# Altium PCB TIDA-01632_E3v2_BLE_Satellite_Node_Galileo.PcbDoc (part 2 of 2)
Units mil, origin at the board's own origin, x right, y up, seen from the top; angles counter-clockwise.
Board outline 3000 x 1875.2 mil, 6 copper layers (Top Layer, Layer2, Layer3, Layer4, Layer5, Bottom Layer), stack 33.151 mil thick; 76 components, 48 nets, 235 pads, 260 vias.
Unrouted connection lines stored in the file: 1.
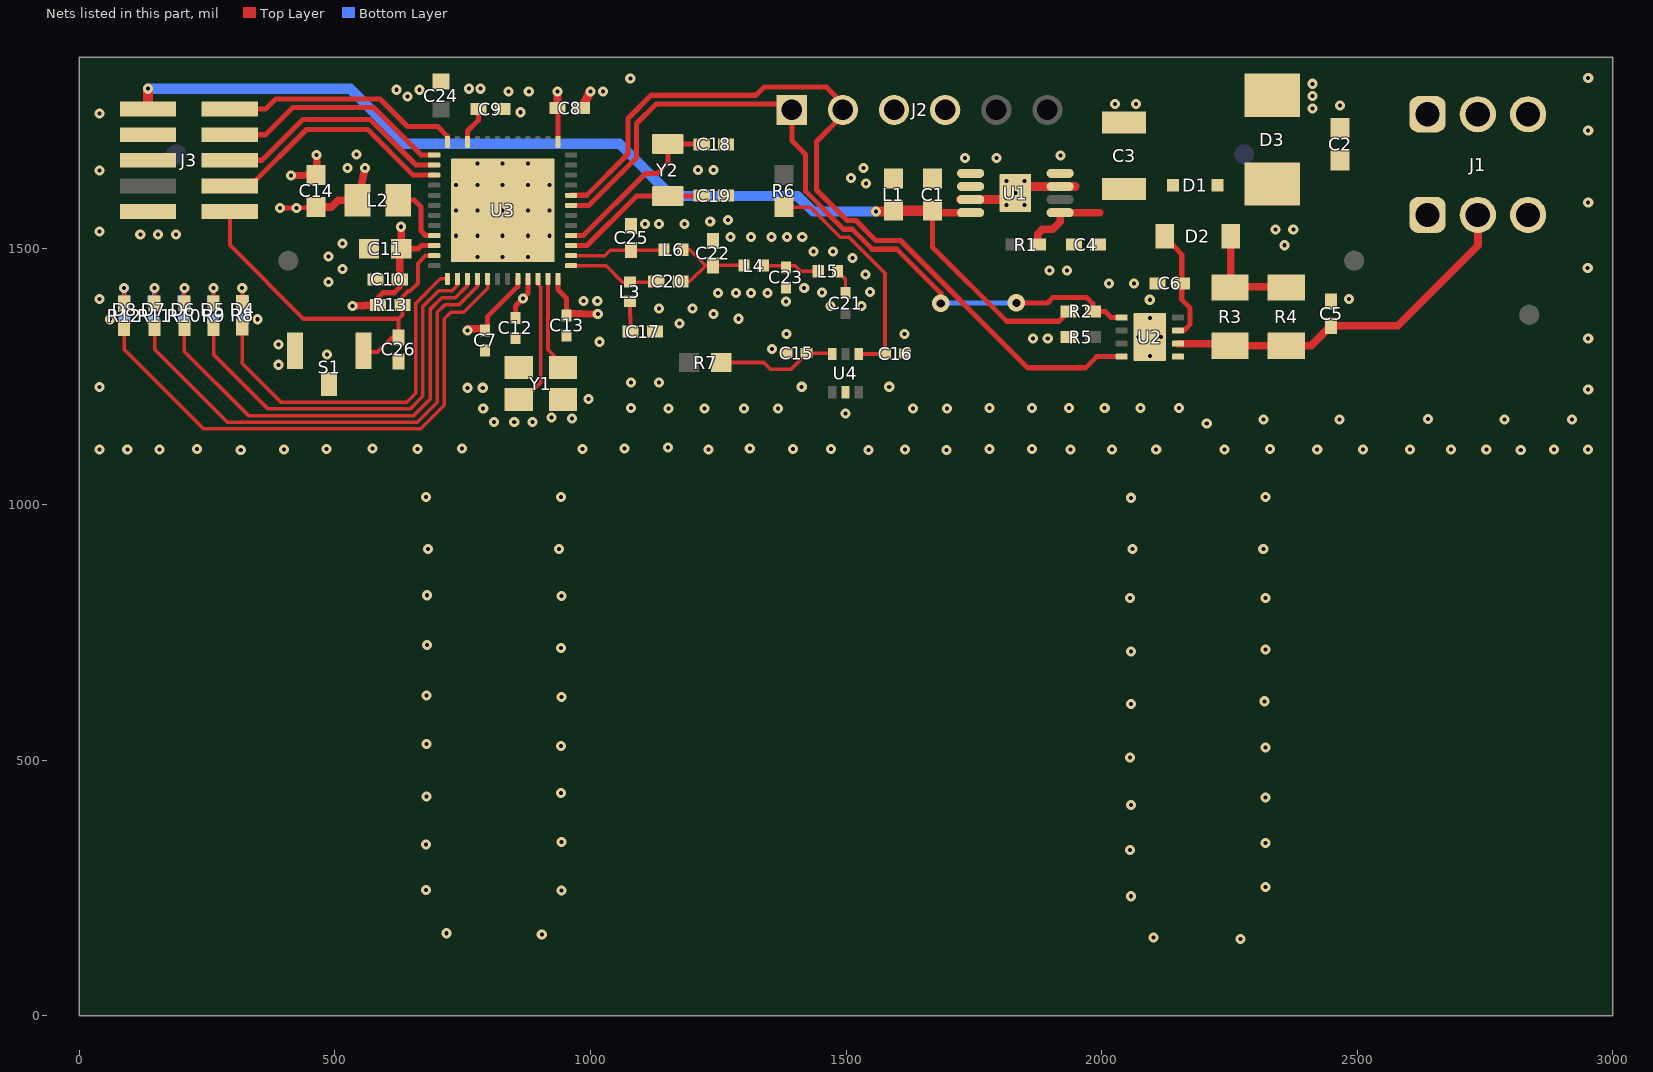
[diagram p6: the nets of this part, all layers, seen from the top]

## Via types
v1: diameter 19.68, hole 7.87, Top Layer to Bottom Layer, tented both sides, 192 vias
v2: diameter 19.68, hole 7.87, Top Layer to Bottom Layer, 63 vias
v3: diameter 34, hole 16, Top Layer to Bottom Layer, tented both sides, 4 vias
v4: diameter 19.68/19.68/19.68/19.68/19.68/19.68 (per signal layer), hole 7.87, Top Layer to Bottom Layer, tented both sides, 1 vias

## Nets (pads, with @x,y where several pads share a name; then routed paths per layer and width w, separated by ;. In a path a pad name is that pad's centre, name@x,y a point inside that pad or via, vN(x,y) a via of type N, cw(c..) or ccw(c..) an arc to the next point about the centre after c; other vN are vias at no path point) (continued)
GND: C1.2 C2.2 C3.1 C4.2 C5.2 C6.2 C7.2 C8.2 C9.2 C10.2 C11.2 C12.2 C13.2 C14.2 C15.2 C16.2 C17.2 C18.2 C19.2 C22.2 C23.2 C24.2 C25.2 C26.2 D3.1 D4.1 D5.2 D6.2 D7.2 D8.1 J1.3 J2.3 J3.3 J3.5 J3.9 R5.1 S1.2 S1.3 U1.3 U1.4 U1.5 U1.6 U1.7 U1.9 U2.5 U2.9@2094.27,1327.59 U3.49@828.41,1575.38 U4.2 Y1.2 Y1.4 | length 322.8
  Top Layer w15: v1(414.41,1643.38) C14.2@463.41,1644.87 v1(464.41,1683.38)
  Top Layer w18: C8.2@983.03,1775.38 v1(1000.41,1808.38) ; U1.7@1724.65,1596.58 U1.7@1743.81,1596.58 U1.9@1818.61,1596.58 ; U1.9@1844.2,1622.17 U1.3@1919.01,1622.17 1948.2,1622.17
  other v1: 2271.75,150.16 2101.93,152.95 904.86,158.51 718.34,161.3 2057.39,233.68 943.84,244.81 677.97,246.21 2320.47,251.77 2056,324.15 677.97,335.29 2320.47,338.07 943.84,339.47 2057.39,411.85 2320.47,427.16 679.37,428.55 942.44,435.51 2056,505.11 2320.47,524.59 942.44,527.38 679.37,531.55 2057.39,609.5 2319.07,615.07 943.84,623.42 679.37,626.21 2057.39,712.51 2320.47,716.68 942.44,719.47 680.76,725.03 2056,816.9 2320.47,816.9 943.84,821.08 680.76,822.47 682.15,912.95 938.27,912.95 2060.17,912.95 2316.29,912.95 2057.39,1013.17 677.97,1014.56 942.44,1014.56 2320.47,1014.56 39.95,1107.4 2020.26,1107.4 2106.88,1107.4 2205.71,1158.46 811,1161 851,1161 2316.91,1166.57 2465.54,1166.57 2788.37,1166.57 2920.26,1166.57 964,1168 2638.76,1167.56 924,1170 1499.02,1178.15 790.34,1188.23 1079.69,1188.38 1153.18,1188.11 1223.46,1188.11 1300.2,1187.99 1367.13,1187.99 1630.87,1187.99 1697.8,1187.99 1780.51,1188.98 1864.17,1188.98 1935.86,1189.11 2006.15,1189.11 2076.44,1189.11 2151.57,1188.98 996,1206 2952,1225 759.41,1228.38 789.41,1228.38 40,1230 1413.39,1230.32 1079.41,1238.38 1134.41,1238.38 389.41,1273.38 484.41,1293.38 1355.3,1304.37 389.41,1313.38 1017.41,1318.38 1865.67,1325.04 1894.67,1325.04 2952,1325 1383.84,1333.9 1614.16,1333.9 1174.41,1354.38 60.02,1362.44 348.41,1362.44 1289.41,1363.38 1240.41,1372.38 1134.41,1383.38 1199.41,1383.38 1469.47,1388.03 1530.5,1388.03 1382.86,1396.89 2094.27,1400.59 40,1402 2484.24,1401.81 1249.41,1413.38 1284.55,1413.38 1314.41,1413.38 1346.44,1413.62 1452.74,1414.61 1547.23,1415.59 1418.29,1423.46 2014.27,1432.59 2063.27,1432.59 487.41,1435.38 1538.37,1450.04 1898.41,1457.38 1932.41,1457.38 515.41,1460.38 2951,1463 1512.78,1482.52 487.41,1485.38 1436.01,1495.32 1474.39,1495.32 2357.41,1507.2 515.41,1510.38 1274.41,1523.38 1314.41,1523.38 1354.41,1523.38 1384.41,1523.38 1414.41,1523.38 119.41,1528.38 154.41,1528.38 189.55,1528.38 40,1534 2339.98,1537.64 2374.98,1537.64 1106.41,1548.38 1134.41,1548.38 1184.41,1548.38 1234.41,1553.38 1269.41,1556.38 2952,1591 40,1653 1210.41,1654.38 1240.41,1654.38 1733,1678 1794,1678 1919.41,1682.38 2952,1732 40,1765 863.41,1767.38 2412.39,1774.84 2466.52,1780.75 2026.56,1783.7 2066.91,1783.7 642.41,1798.38 2412.39,1799.45 839.41,1808.38 879.41,1808.38 1024.41,1808.38 620.41,1811.38 665.41,1811.38 2412.39,1823.07 1078,1833 2952,1834
  other v2: 316,1107 1544,1107 1697,1107 2240.73,1107.4 2421.84,1107.4 2511.4,1107.4 2602.94,1107.4 2683.65,1107.4 2752.54,1107.4 2820,1107 2885.42,1107.4 2951.36,1107.4 94,1108 157,1108 401,1108 1231,1108 1615,1108 1939,1108 230.22,1108.53 483.56,1108.53 661.73,1108.53 748.61,1109.36 984.66,1108.53 1396,1109 1471,1109 1781,1109 1864,1109 2329.27,1108.53 574.03,1109.92 1066.78,1109.92 1311.76,1109.92 1151.69,1111.32 887,1161 2094.27,1290.19 2072.61,1327.59 2115.92,1327.59 2094.27,1364.99 778.8,1483.84 828.41,1483.84 878.01,1483.84 736.87,1525.77 778.8,1525.77 828.41,1525.77 878.01,1525.77 919.94,1525.77 736.87,1575.38 778.8,1575.38 828.41,1575.38 878.01,1575.38 919.94,1575.38 1813.69,1585.75 1849.12,1585.75 1831.41,1609.38 736.87,1624.98 778.8,1624.98 828.41,1624.98 878.01,1624.98 919.94,1624.98 1813.69,1633 1849.12,1633 778.8,1666.91 828.41,1666.91 878.01,1666.91
  other v4: 1584.61,1230.32
LED_Blue: R9.2 U3.38 | length 789.2
  Top Layer w7: R9.2@262.78,1345.71 262.78,1293.54 369.32,1187 647.64,1187 672.28,1211.64 672.28,1387.45 703.21,1418.38 729.41,1418.38 739.83,1428.79 U3.38@739.83,1441.52
LED_Green: R8.2 U3.37 | length 706.6
  Top Layer w7: R8.2@318.88,1346.69 318.88,1275.83 394.71,1200 640.84,1200 658.28,1217.44 658.28,1393.25 706.55,1441.52 U3.37@720.14,1441.52
LED_Orange: R11.2 U3.40 | length 953.9
  Top Layer w7: R11.2@147.62,1339.14 147.62,1303.39 290.01,1161 661.23,1161 700.28,1200.04 700.28,1375.85 714.8,1390.38 742.44,1390.38 774.38,1422.32 ; 774.38,1422.35 779.2,1427.16 U3.40@779.2,1441.52
LED_Red: R12.2 U3.41 | length 1048.5
  Top Layer w7: R12.2@87.81,1344.81 87.81,1303.16 242.97,1148 668.03,1148 714.28,1194.25 714.28,1363.25 727.41,1376.38 752.41,1376.38 798.88,1422.85 U3.41@798.88,1441.52
LED_Yellow: R10.2 U3.39 | length 873.5
  Top Layer w7: R10.2@205.69,1345.71 205.69,1299.45 331.14,1174 654.43,1174 686.28,1205.84 686.28,1381.65 709.01,1404.38 735.21,1404.38 736.21,1405.38 736.44,1405.38 754.7,1423.63 759.51,1428.48 U3.39@759.51,1441.52
LIN: C5.1 J1.2 R3.1 R4.1 U2.6 | length 740.1
  Top Layer w15: U2.6@2149.38,1314.79 R3.1@2246.97,1314.79 ; R3.1@2251.27,1310.5 R4.1@2361.27,1310.5 2409.66,1310.5 C5.1@2448.8,1349.65 2579.28,1349.65 2736.2,1506.57 J1.2@2736.2,1582.91
NetC17_1: C17.1 L3.2 | length 59.9
  Top Layer w7.87: L3.2@1077.41,1397.67 1077.41,1368.38 1078.79,1367 C17.1@1078.79,1338.38
NetC20_1: C20.1 C22.1 L4.1 L6.2 | length 194.9
  Top Layer w6.75: C20.1@1176.03,1436.38 1194.41,1436.38 1225.41,1467.38 ; L6.2@1181.11,1498.38 1194.41,1498.38 1225.41,1467.38 ; 1226.03,1468 1225.41,1467.38 ; L4.1@1300.09,1468 C22.1@1239.41,1468 1225.41,1467.38
NetC21_2: C21.2 L5.2 | length 45.4
  Top Layer w6.75: L5.2@1483.11,1456.38 1499,1440.48 C21.2@1499,1417.56
NetC23_1: C23.1 L4.2 L5.1 | length 112.2
  Top Layer w6.75: L4.2@1338.11,1467.38 1400.41,1467.38 1411.41,1456.38 L5.1@1445.71,1456.38
NetD2_1: D2.1 R3.2 R4.2 | length 205.5
  Top Layer w15: D2.1@2252.73,1524.56 2252.73,1426.14 R4.2@2359.8,1426.14
NetD4_2: D4.2 R8.1 | length 54.5
  Top Layer w7: R8.1@318.88,1393.94 v1(318.88,1423.46)
  Bottom Layer w7: v1(318.88,1423.46) 319.87,1422.48 D4.2@319.87,1398.86
NetD5_1: D5.1 R9.1 | length 55.5
  Top Layer w7: R9.1@262.78,1392.95 v1(262.78,1423.46)
  Bottom Layer w7: D5.1@261.8,1398.86 261.8,1422.48 v1(262.78,1423.46)
NetD6_1: D6.1 R10.1 | length 55.9
  Top Layer w7: R10.1@205.69,1392.95 v1(205.69,1423.46)
  Bottom Layer w7: D6.1@203.72,1398.86 203.72,1421.5 v1(205.69,1423.46)
NetD7_1: D7.1 R11.1 | length 55.9
  Top Layer w7: R11.1@147.62,1392.95 v1(147.62,1423.46)
  Bottom Layer w7: D7.1@145.65,1398.86 145.65,1421.5 v1(147.62,1423.46)
NetD8_2: D8.2 R12.1 | length 55.2
  Top Layer w7: R12.1@87.81,1392.7 v1(87.81,1423.24)
  Bottom Layer w7: v1(87.81,1423.24) 88.57,1422.48 D8.2@88.57,1398.86
NetL2_1: L2.1 U3.33 | length 126.3
  Top Layer w10: L2.1@624.41,1595.38 655.41,1595.38 668.41,1582.38 668.41,1535.38 677.62,1526.16 U3.33@694.55,1526.16
NetU3_46: U3.46 Y1.3 | length 264.3
  Top Layer w7: Y1.3@861.1,1196.88 902.99,1238.77 902.99,1425.09 897.31,1430.77 U3.46@897.31,1441.52
NetU3_47: U3.47 Y1.1 | length 182.2
  Top Layer w7: U3.47@916.99,1441.52 916.99,1302.79 Y1.1@947.71,1272.07
nRESET: C26.1 J3.10 R13.1 S1.1 U3.35 | length 726.3
  Top Layer w7.87: J3.10@294.53,1573.38 294.53,1507.26 438.41,1363.38 624.41,1363.38 ; S1.1@566.34,1298.38 583.41,1298.38 612.03,1327 C26.1@624.41,1327 624.41,1363.38 ; U3.35@694.55,1486.79 677.83,1486.79 662.41,1471.38 662.41,1432.73 647.31,1417.63 643.66,1417.63 632.03,1406 R13.1@632.03,1390.38 632.03,1371 624.41,1363.38
RF_N: C25.1 L6.1 U3.2 | length 186.2
  Top Layer w6.75: U3.2@962.27,1486.79 1027.83,1486.79 1038.79,1497.75 C25.1@1079.41,1497.75 1143.09,1497.75 L6.1@1143.71,1498.38
RF_P: C20.2 L3.1 U3.1 | length 178.5
  Top Layer w6.75: U3.1@962.27,1467.11 1030.68,1467.11 1062.71,1435.08 L3.1@1077.41,1435.08 C20.2@1127.49,1435.08
RXD_LIN: J2.1 R2.1 U2.1 U3.7 | length 1486
  Top Layer w10: U3.7@962.27,1585.22 997.17,1585.22 1090.41,1678.46 1090.41,1745.38 1128.73,1783.7 1394.67,1783.7 1394.67,1710.87 1421.06,1684.47 1421.06,1612.68 1495.35,1538.4 1512.3,1538.4 1551.32,1499.38 1599.37,1499.38 1685.41,1413.33 v3(1685.41,1393.38) ; v3(1833.41,1394.38) 1894.05,1394.38 1904.27,1404.59 1971.27,1404.59 1982.89,1392.97 R2.1@1982.89,1377.59 2007.27,1377.59 2018.88,1365.97 U2.1@2039.15,1365.97
  Bottom Layer w10: v3(1685.41,1393.38) 1686.41,1394.38 v3(1833.41,1394.38)
TCK: J3.4 U3.25 | length 460.4
  Top Layer w10: J3.4@294.53,1723.38 364.41,1723.38 417.41,1776.38 576.41,1776.38 669.14,1683.64 U3.25@694.55,1683.64
TDI: J3.8 U3.27 | length 482.5
  Top Layer w10: J3.8@294.53,1623.38 334.41,1623.38 444.41,1733.38 564.41,1733.38 653.51,1644.27 U3.27@694.55,1644.27
TDO: J3.6 U3.26 | length 470.2
  Top Layer w10: J3.6@294.53,1673.38 357.41,1673.38 437.41,1753.38 569.41,1753.38 658.83,1663.96 U3.26@694.55,1663.96
TMS: J3.2 U3.24 | length 475.4
  Top Layer w10: J3.2@294.53,1773.38 364.41,1773.38 384.41,1793.38 588.41,1793.38 642.41,1739.38 701.41,1739.38 720.14,1720.64 U3.24@720.14,1709.23
TXD_LIN: J2.2 U2.4 U3.8 | length 1614.7
  Top Layer w10: U3.8@962.27,1604.9 992.81,1604.9 1073.41,1685.5 1073.41,1755.38 1118.73,1800.7 1323.7,1800.7 1340,1817 1461.37,1817 1494.67,1783.7 1494.67,1762.64 1442.41,1710.38 1442.41,1615.38 1502.39,1555.4 1519.35,1555.4 1558.37,1516.38 1606.41,1516.38 1855.2,1267.59 1968.81,1267.59 1990.42,1289.2 U2.4@2039.15,1289.2
V3p3: C1.1 J3.1 L1.2 R2.2 U1.8 | length 2149
  Top Layer w10: C1.1@1669.41,1574.88 1669.41,1503.38 1814.28,1358.5 1916.56,1358.5 R2.2@1935.64,1377.59
  Top Layer w15: C1.1@1673.3,1570.99 U1.8@1743.81,1570.99
  Top Layer w20: J3.1@134.29,1773.38 v1@134.29,1813.26 ; v1(1558.41,1573.38) L1.2@1591.4,1573.38 ; L1.2@1592.91,1574.88 C1.1@1669.41,1574.88
  Bottom Layer w20: v1(134.41,1813.38) 530.41,1813.38 637.84,1705.94 1056.84,1705.94 1159.41,1603.38 1405.41,1603.38 1435.41,1573.38 v1(1558.41,1573.38)
VBATT: C2.1 D1.2 D3.2 J1.1
VCTRL1: C16.1 R6.2 U4.4 | length 460.9
  Top Layer w7: R6.2@1378.58,1581.88 1429.94,1581.88 1488.93,1522.9 1505.88,1522.9 1576.32,1452.46 C16.1@1576.32,1295.32 ; U4.4@1524.59,1294.4 1575.4,1294.4 C16.1@1576.32,1295.32 ; C16.1@1576.32,1295 C16.1@1576.32,1295.32
VCTRL2: C15.1 R7.2 U4.6 | length 234
  Top Layer w7: R7.2@1255.89,1277.8 1339.2,1277.8 1352,1265 1393,1265 C15.1@1423,1295 ; C15.1@1422.68,1296 U4.6@1471.81,1296
VDDR: C12.1 C13.1 C14.1 L2.2 U3.45 U3.48 | length 457.8
  Top Layer w10: v1(392.41,1580.38) v1(425.41,1580.38) C14.1@463.41,1581.88 C14.1@446.03,1581.88 ; C12.1@853.41,1369 853.41,1388.38 v1(868.41,1403.38) 877.62,1412.59 U3.45@877.62,1441.52 ; U3.48@936.68,1441.52 936.68,1420.11 953.41,1403.38 C13.1@953.41,1374
  Top Layer w15: C14.1@463.41,1581.88 492.91,1581.88 506.41,1595.38 L2.2@544.41,1595.38 v1(559.41,1658.38) ; C13.1@953.41,1374 v1(1014.41,1372.38)
  other v1: 986.41,1398.38 1013.41,1398.38 524.41,1658.38 542.41,1684.38
VDDS: C7.1 C8.1 C9.1 C10.1 C11.1 J2.4 L1.1 R13.2 U3.13 U3.22 U3.34 U3.44 | length 630.8
  Top Layer w10: R13.2@584.79,1390.38 584.79,1404.75 594.22,1414.19 616.22,1414.19 627.03,1425 C10.1@627.03,1440.38 ; C11.1@627.03,1497.5 C11.1@629.9,1500.38 663.41,1500.38 669.51,1506.48 U3.34@694.55,1506.48 ; U3.22@759.51,1709.23 759.51,1730.48 780.79,1751.75 C9.1@780.79,1773.38 ; C7.1@798.41,1344 798.41,1367.42 857.94,1426.94 U3.44@857.94,1441.52 ; U3.13@936.68,1709.23 C8.1@936.68,1774.49
  Top Layer w15: v1(534.41,1388.38) R13.2@584.79,1390.38 ; C10.1@627.03,1440.38 C11.1@627.03,1497.5 ; C11.1@629.9,1500.38 v1@629.9,1542.88 ; v1(759.41,1340.38) 763.03,1344 C7.1@794,1344 ; C8.1@935.79,1775.38 v1@935.79,1808
  other v1: 629.41,1543.38 1539.55,1628.38 1509.41,1638.38 1534.41,1658.38 935.41,1808.38 762.41,1813.38 785.41,1813.38
VSUP: C3.2 C4.1 C6.1 D1.1 D2.2 R1.1 U1.1 U2.7 | length 390
  Top Layer w10: D2.2@2123.8,1524.56 2156.89,1489 C6.1@2156.89,1432.59 2156.89,1400.79 2173.27,1384.41 2173.27,1352.59 2161.06,1340.38 U2.7@2149.38,1340.38
  Top Layer w15: R1.1@1875.06,1508.51 1875.06,1529.03 1884.41,1538.38 1904.41,1538.38 1919.01,1552.97 U1.1@1919.01,1570.99 1995.93,1570.99
X32K_Q1: C19.1 U3.3 Y2.2 | length 294.4
  Top Layer w10: U3.3@962.27,1506.48 993.51,1506.48 1090.23,1603.19 Y2.2@1151.41,1603.19 C19.1@1216.6,1603.19
X32K_Q2: C18.1 U3.4 Y2.1 | length 350.4
  Top Layer w10: U3.4@962.27,1526.16 986.2,1526.16 1107.65,1647.62 1130.65,1647.62 1151.41,1668.38 Y2.1@1151.41,1705.56 C18.1@1216.6,1705.56
pads on no net: FID1.1 FID2.1 FID3.1 FID4.1 FID5.1 FID6.1 J3.7 LBL1.0 U2.3 U2.8 U2.9@2094.27,1302.59 U2.9@2094.27,1352.59 U3.5 U3.12 U3.14 U3.15 U3.16 U3.17 U3.18 U3.19 U3.20 U3.21 U3.28 U3.29 U3.30 U3.31 U3.32 U3.36 U3.43 U3.49@754,1500.97 U3.49@754,1550.57 U3.49@754,1600.18 U3.49@754,1649.78 U3.49@803.6,1500.97 U3.49@803.6,1550.57 U3.49@803.6,1600.18 U3.49@803.6,1649.78 U3.49@853.21,1500.97 U3.49@853.21,1550.57 U3.49@853.21,1600.18 U3.49@853.21,1649.78 U3.49@902.82,1500.97 U3.49@902.82,1550.57 U3.49@902.82,1600.18 U3.49@902.82,1649.78

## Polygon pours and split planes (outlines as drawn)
GND on Layer2 "LAYER2-GND 4" (solid, pour order 541): 220.47,1072.85 220.47,88.58 181.08,88.61 181.11,1072.85 141.74,1072.85 141.72,88.61 102.35,88.61 102.35,1072.83 62.99,1072.83 62.99,88.61 23.62,88.61 23.59,1072.85 23.59,1112.22 220.47,1112.22 220.47,1072.85
GND on Layer2 "LAYER2-GND 5" (solid, pour order 539): 1440.93,1072.85 1440.93,88.58 1401.56,88.58 1401.56,1072.85 1362.2,1072.85 1362.2,88.58 1322.83,88.58 1322.83,1072.85 1283.47,1072.85 1283.44,88.61 1244.08,88.61 1244.11,1072.85 1204.71,1072.83 1204.71,88.61 1165.35,88.61 1165.32,1072.85 1125.96,1072.85 1125.99,88.61 1086.59,88.58 1086.59,1072.85 1047.23,1072.85 1047.23,88.58 1007.87,88.58 1007.87,1072.85 968.5,1072.85 968.47,206.7 850.38,88.61 771.65,88.61 653.53,206.73 653.53,1072.85 614.17,1072.85 614.17,88.58 574.8,88.58 574.8,1072.85 535.44,1072.85 535.41,88.61 496.05,88.61 496.05,1072.83 456.68,1072.83 456.68,88.61 417.32,88.61 417.29,1072.85 377.93,1072.85 377.96,88.61 338.56,88.58 338.56,1072.85 299.2,1072.85 299.2,88.58 259.84,88.58 259.84,1072.85 220.47,1072.85 220.47,88.58 181.08,88.61 181.11,1072.85 181.11,1112.22 1440.93,1112.22 1440.93,1072.85
GND on Layer2 "LAYER2-GND 7" (solid, pour order 537): 1598.41,1072.83 1598.41,88.61 1559.05,88.61 1559.05,1072.83 1519.65,1072.85 1519.68,88.61 1480.29,88.58 1480.29,1072.85 1440.93,1072.85 1440.93,88.58 1401.56,88.58 1401.56,1072.85 1401.56,1112.22 1598.44,1112.22 1598.41,1072.83
GND on Layer2 "LAYER2-GND 9" (solid, pour order 535): 2818.89,1072.85 2818.89,88.58 2779.53,88.58 2779.53,1072.85 2740.17,1072.85 2740.14,88.61 2700.77,88.61 2700.77,1072.83 2661.41,1072.83 2661.41,88.61 2622.05,88.61 2622.02,1072.85 2582.65,1072.85 2582.65,88.58 2543.29,88.58 2543.29,1072.85 2503.92,1072.85 2503.92,88.58 2464.56,88.58 2464.56,1072.85 2425.2,1072.85 2425.2,88.58 2385.8,88.61 2385.83,1072.85 2346.47,1072.85 2346.44,206.7 2228.35,88.61 2149.59,88.58 2031.47,206.7 2031.5,1072.85 1992.14,1072.85 1992.11,88.61 1952.74,88.61 1952.74,1072.83 1913.38,1072.83 1913.38,88.61 1874.02,88.61 1873.99,1072.85 1834.62,1072.85 1834.62,88.58 1795.26,88.58 1795.26,1072.85 1755.89,1072.85 1755.89,88.58 1716.53,88.58 1716.53,1072.85 1677.17,1072.85 1677.17,88.58 1637.77,88.61 1637.8,1072.85 1598.41,1072.83 1598.41,88.61 1559.05,88.61 1559.05,1072.83 1559.02,1112.22 2818.89,1112.22 2818.89,1072.85
GND on Layer2 "LAYER2-GND 4" (solid, pour order 533): 2976.38,1072.83 2976.38,88.55 2936.99,88.58 2937.01,1072.83 2897.65,1072.83 2897.62,88.58 2858.26,88.58 2858.26,1072.8 2818.89,1072.8 2818.89,88.58 2779.53,88.58 2779.5,1072.83 2779.5,1112.19 2976.38,1112.19 2976.38,1072.83
GND on Layer2 "LAYER2_GND_P240" (solid, remove dead copper, pour order 240): 24,1108 23,1890 2975.38,1890 2975.38,1108
GND on Layer5 "LAYER5-GND 6" (solid, pour order 551): 2818.89,1072.85 2818.89,88.58 2779.53,88.58 2779.53,1072.85 2740.17,1072.85 2740.14,88.61 2700.77,88.61 2700.77,1072.83 2661.41,1072.83 2661.41,88.61 2622.05,88.61 2622.02,1072.85 2582.65,1072.85 2582.65,88.58 2543.29,88.58 2543.29,1072.85 2503.92,1072.85 2503.92,88.58 2464.56,88.58 2464.56,1072.85 2425.2,1072.85 2425.2,88.58 2385.8,88.61 2385.83,1072.85 2346.47,1072.85 2346.44,206.7 2228.35,88.61 2149.59,88.58 2031.47,206.7 2031.5,1072.85 1992.14,1072.85 1992.11,88.61 1952.74,88.61 1952.74,1072.83 1913.38,1072.83 1913.38,88.61 1874.02,88.61 1873.99,1072.85 1834.62,1072.85 1834.62,88.58 1795.26,88.58 1795.26,1072.85 1755.89,1072.85 1755.89,88.58 1716.53,88.58 1716.53,1072.85 1677.17,1072.85 1677.17,88.58 1637.77,88.61 1637.8,1072.85 1598.41,1072.83 1598.41,88.61 1559.05,88.61 1559.05,1072.83 1559.02,1112.22 2818.89,1112.22 2818.89,1072.85
GND on Layer5 "LAYER5-GND 7" (solid, pour order 549): 1598.41,1072.83 1598.41,88.61 1559.05,88.61 1559.05,1072.83 1519.65,1072.85 1519.68,88.61 1480.29,88.58 1480.29,1072.85 1440.93,1072.85 1440.93,88.58 1401.56,88.58 1401.56,1072.85 1401.56,1112.22 1598.44,1112.22 1598.41,1072.83
GND on Layer5 "LAYER5-GND 8" (solid, pour order 547): 1440.93,1072.85 1440.93,88.58 1401.56,88.58 1401.56,1072.85 1362.2,1072.85 1362.2,88.58 1322.83,88.58 1322.83,1072.85 1283.47,1072.85 1283.44,88.61 1244.08,88.61 1244.11,1072.85 1204.71,1072.83 1204.71,88.61 1165.35,88.61 1165.32,1072.85 1125.96,1072.85 1125.99,88.61 1086.59,88.58 1086.59,1072.85 1047.23,1072.85 1047.23,88.58 1007.87,88.58 1007.87,1072.85 968.5,1072.85 968.47,206.7 850.38,88.61 771.65,88.61 653.53,206.73 653.53,1072.85 614.17,1072.85 614.17,88.58 574.8,88.58 574.8,1072.85 535.44,1072.85 535.41,88.61 496.05,88.61 496.05,1072.83 456.68,1072.83 456.68,88.61 417.32,88.61 417.29,1072.85 377.93,1072.85 377.96,88.61 338.56,88.58 338.56,1072.85 299.2,1072.85 299.2,88.58 259.84,88.58 259.84,1072.85 220.47,1072.85 220.47,88.58 181.08,88.61 181.11,1072.85 181.11,1112.22 1440.93,1112.22 1440.93,1072.85
GND on Layer5 "LAYER5-GND 9" (solid, pour order 545): 220.47,1072.85 220.47,88.58 181.08,88.61 181.11,1072.85 141.74,1072.85 141.72,88.61 102.35,88.61 102.35,1072.83 62.99,1072.83 62.99,88.61 23.62,88.61 23.59,1072.85 23.59,1112.22 220.47,1112.22 220.47,1072.85
GND on Layer5 "LAYER2-GND 4" (solid, pour order 543): 2976.38,1072.83 2976.38,88.55 2936.99,88.58 2937.01,1072.83 2897.65,1072.83 2897.62,88.58 2858.26,88.58 2858.26,1072.8 2818.89,1072.8 2818.89,88.58 2779.53,88.58 2779.5,1072.83 2779.5,1112.19 2976.38,1112.19 2976.38,1072.83
GND on Layer5 "LAYER5_GND_P241" (solid, remove dead copper, pour order 241): 24,1108 24,1874.98 2976.21,1875 2976.21,1108
GND on Layer3 "LAYER3-GND 3" (solid, pour order 557): 948.74,923.25 948.74,903.54 881.81,903.54 881.81,194.87 842.45,155.51 842.45,37.41 1417.26,37.41 1417.24,21.69 826.69,21.66 826.69,167.31 862.13,202.75 862.13,923.22 948.74,923.25
GND on Layer3 "LAYER3-GND 2" (solid, pour order 555): 759.77,923.25 759.77,202.78 795.2,167.34 795.18,21.66 204.66,21.66 204.66,37.41 779.42,37.41 779.45,155.54 740.08,194.9 740.08,903.57 673.16,903.57 673.13,923.25 759.77,923.25
GND on Layer3 "LAYER3-GND 2" (solid, pour order 527): 2137.79,923.25 2137.79,202.78 2173.23,167.34 2173.2,21.66 1582.68,21.66 1582.68,37.41 2157.44,37.41 2157.47,155.54 2118.11,194.9 2118.11,903.57 2051.18,903.57 2051.15,923.25 2137.79,923.25
GND on Layer3 "LAYER3-GND 3" (solid, pour order 525): 2326.76,923.25 2326.76,903.54 2259.83,903.54 2259.83,194.87 2220.47,155.51 2220.47,37.41 2795.29,37.41 2795.26,21.69 2204.71,21.66 2204.71,167.31 2240.15,202.75 2240.15,923.22 2326.76,923.25
VDDS on Layer3 "LAYER3_VDDS_P245" (solid, pour order 245): 23,1331.93 23,1875 2976,1875 2976,1331.93
Antenna1 on Layer4 "LAYER4-ANT6" (solid, pour order 523): 814.94,1072.85 814.94,1045.63 811.91,1038.19 798.52,1024.41 798.52,813.39 806.76,806.66 816.11,806.66 824.85,814.06 824.85,922.97 825.16,1007.35 825.16,1007.4 828.03,1013.45 837.52,1020.99 843.81,1023.16 855.45,1022.99 861.79,1020.88 870.76,1014.31 873.82,1008.35 873.77,923.22 881.87,923.25 881.89,194.9 838.49,151.67 783.43,151.67 740.14,194.9 740.28,923.25 759.93,923.25 759.96,813.37 759.96,807.35 759.93,801.03 759.82,202.78 791.36,171.35 830.78,171.35 862.21,202.78 862.21,923.25 865.89,923.25 865.94,1008.1 856.34,1015.14 842.98,1015.31 833.01,1007.35 832.76,919.63 832.76,814.12 829.92,808.05 821.73,801.09 815.42,798.78 807.48,798.81 801.19,801.03 793.53,807.35 790.67,813.34 790.64,1024 793.17,1030.2 807.09,1045.29 807.09,1072.85 814.94,1072.85
Antenna2 on Layer4 "LAYER4-ANT5" (solid, pour order 521): 2192.91,1072.85 2192.91,1045.63 2189.87,1038.19 2176.48,1024.41 2176.48,813.39 2184.72,806.66 2194.05,806.69 2202.82,814.06 2202.82,922.97 2203.1,1007.32 2203.1,1007.43 2205.99,1013.45 2215.46,1021.02 2221.78,1023.16 2233.41,1022.99 2239.76,1020.88 2248.73,1014.31 2251.76,1008.38 2251.7,923.25 2259.83,923.25 2259.83,194.87 2216.46,151.67 2161.37,151.69 2118.11,194.9 2118.22,923.22 2137.9,923.25 2137.9,813.34 2137.9,807.33 2137.84,801.03 2137.79,202.78 2169.33,171.35 2208.75,171.35 2240.15,202.75 2240.15,923.22 2243.85,923.25 2243.88,1008.07 2234.28,1015.12 2220.92,1015.28 2210.98,1007.35 2210.7,919.6 2210.7,814.09 2207.89,808.05 2199.67,801.06 2193.38,798.78 2185.42,798.78 2179.1,801.03 2171.47,807.33 2168.61,813.37 2168.61,1024 2171.14,1030.2 2185.03,1045.26 2185.03,1072.83 2192.91,1072.85
VDDR on Layer4 "LAYER4_VDDR_P249" (solid, remove dead copper, pour order 249): 24.41,1331.93 24.41,1890 2974.41,1890 2974.41,1331.93
VDDS on Top Layer "TOP_LAYER_VDDS_P223" (solid, remove dead copper, pour order 223): 1564.41,1608.38 1624.41,1608.38 1624.41,1673.38 1564.41,1673.38 1554.41,1683.38 1519.41,1683.38 1490.91,1664.38 1490.91,1619.88 1529.41,1598.38 1554.41,1598.38
VDDR on Top Layer "TOP_LAYER_VDDR_P247" (solid, remove dead copper, pour order 247): 929.41,1353.38 1029.41,1353.38 1029.41,1413.38 929.41,1423.38
VDDR on Top Layer "TOP_LAYER_VDDR_P220" (solid, remove dead copper, pour order 220): 283.8,1553.38 584.41,1553.38 584.41,1691.84 468.85,1745.17
VDDS on Top Layer "TOP_LAYER_VDDS_P251" (solid, remove dead copper, pour order 251): 804.41,1753.38 804.41,1788.38 814.41,1798.38 814.41,1828.38 744.41,1828.38 744.41,1753.38
VBATT on Top Layer "Top Layer-No Net" (solid, pour order 561): 2587.58,1880.16 2587.58,1739.41 2544.28,1696.1 2235.22,1696.1 2211.6,1672.48 2211.6,1605.55 2232.27,1584.88 2542.31,1584.88 2602.58,1524.61 2667.07,1524.61 2686.01,1543.54 2686.01,1880.16
VSUP on Top Layer "Top Layer-No Net 1" (solid, pour order 565): 1990.14,1642.95 1982.27,1635.08 1982.27,1496.3 1988.17,1490.39 2149.59,1490.39 2155.5,1496.3 2155.5,1637.05 2149.59,1642.95
GND on Top Layer "Top Layer-No Net 2" (solid, pour order 567): 23,1875 23.95,1109 2976.38,1109 2976.38,1875
GND on Bottom Layer "Top Layer-No Net 2" (solid, pour order 569): 23,1875 23,1109 2976.38,1109 2976.38,1875

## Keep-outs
Keep-Out Layer:
  text ".Layer_Name" at 577,-858.49 h60

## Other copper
Top Layer:
  pour cut-out: 89.41,1803.38 89.41,1828.38 34.41,1828.38 34.41,1733.38 64.41,1733.38 64.41,1803.38
  pour cut-out: 159.41,1798.38 204.41,1798.38 204.41,1733.38 224.41,1733.38 224.41,1798.38 374.41,1798.38 379.41,1803.38 599.41,1803.38 599.41,1833.38 159.41,1833.38
  pour cut-out: 1445.87,1317.91 1453.74,1317.91 1453.74,1311.02 1445.87,1311.02
  pour cut-out: 1544.29,1317.91 1553.15,1317.91 1553.15,1310.04 1544.29,1310.04
  pour cut-out: 1445.87,1280.51 1453.74,1280.51 1453.74,1273.62 1445.87,1273.62
  pour cut-out: 1544.29,1279.53 1553.15,1279.53 1553.15,1272.64 1544.29,1272.64
  text ".Layer_Name" at 577,-858.49 h60
Bottom Layer:
  text ".Layer_Name" at 577,-858.49 h60

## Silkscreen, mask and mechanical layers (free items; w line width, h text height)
Top Overlay:
  circle w10: c124.94,1809.9 r4.24
  text "VDDS" at 1647.62,1837.83 h40
  text "DIO6" at 1764.75,1837.83 h40
  text "DIO5" at 1864.16,1837.83 h40
  text "RXD" at 1362.19,1836.85 h40
  text "GND" at 1559.04,1836.85 h40
  text "TXD" at 1460.61,1835.87 h40
  text "Vbat" at 2580.71,1431.1 h60
  text "GND" at 2815.94,1431.1 h60
  text "LIN" at 2719.49,1430.12 h60
  text "nRST" at 370,1216 h30
  text "Antenna 2" at 1986.22,933.07 h100
  text "Antenna 1" at 614.17,929.13 h100
  text ".Layer_Name" at 577,-858.49 h60
Bottom Overlay:
  rectangle: 1002.68,428.29 1302.68,528.29
  lines w5: 62.98,1344.72 62.98,1419.53 120.06,1419.53 ; 120.06,1344.72 120.06,1419.53 ; 177.15,1344.72 177.15,1419.53 ; 234.24,1344.72 234.24,1419.53 ; 291.32,1344.72 291.32,1419.53 ; 348.41,1344.72 348.41,1419.53 291.32,1419.53 ; 120.06,1419.53 177.15,1419.53 ; 177.15,1419.53 234.24,1419.53 ; 234.24,1419.53 291.32,1419.53
  text "RXD" at 1427,1695 h40
  text "TXD" at 1530,1695 h40
  text "GND" at 1631,1695 h40
  text "VDDS" at 1743,1695 h40
  text "DIO6" at 1832,1695 h40
  text "DIO5" at 1934,1695 h40
  text "Vbat" at 2691,1476 h60
  text "LIN" at 2781,1476 h60
  text "GND" at 2915,1476 h60
  text "Status LEDs" at 361,1433 h65
  text "TIDA-01632E3" at 1997.68,443.29 h108.27
  text ".Layer_Name" at 577,-858.49 h60
Top Paste:
  text ".Layer_Name" at 577,-858.49 h60
Bottom Paste:
  text ".Layer_Name" at 577,-858.49 h60
Top Solder:
  text ".Layer_Name" at 577,-858.49 h60
  text ".Layer_Name" at 577,-858.49 h60
Bottom Solder:
  text ".Layer_Name" at 577,-858.49 h60
Drill Guide:
  text ".Layer_Name" at 577,-858.49 h60
M1 Board Outline:
  the board outline again, w10
  text ".Layer_Name" at 577,-858.49 h60
M2 Board Dimensions:
  rectangle: 0,-325 125,-200
  rectangle: 125,-450 500,-325
  lines w7: 0,-325 1000,-325 ; 125,-450 125,-200 ; 250,-450 250,-200 ; 500,-450 500,-200 ; 750,-450 750,-200 ; 0,-450 1000,-450 1000,-200 0,-200 0,-450
  text ".Layer_Name" at 577,-858.49 h60
M3 3D STEP Top:
  text ".Layer_Name" at 577,-858.49 h60
M4 3D STEP Bottom:
  text ".Layer_Name" at 577,-858.49 h60
M5 Assembly Top:
  lines w10: -292,-930.17 6308,-930.17 ; -292,-726.83 6310,-726.83 ; -292,-523.5 -292,-1133.5 3713,-1133.5 6310,-1133.5 6310,-523.5 -291.5,-523.5 -291.5,-1133.5 1284,-1133.5 ; 2173,-1133.5 2173,-523.5 ; 3440,-726.83 3440,-523.5 ; 4280,-726.83 4280,-523.5 ; 4902,-1140 4902,-937.17
  text "COMPONENTS MARKED 'DNP' SHOULD NOT BE POPULATED." at 1153.5,-318.5 h60
  text "ASSEMBLY VARIANT:" at 1153,-434 h60
  text ".VariantName" at 2189,-434 h60
  text "PCB VIEWED FROM TOP SIDE" at -228.5,-655.67 h60
  text "BOARD #:" at 2248,-655.67 h60
  text ".PRJ_Number" at 2793.5,-655.67 h60
  text "REV:" at 3638,-655.67 h60
  text ".PCB_Rev" at 3929.5,-655.67 h60
  text "SVN REV:" at 4476,-655.67 h60
  text ".VersionControl_RevNumber" at 4982,-655.67 h60
  text "TID #:" at 2248,-859 h60
  text ".TID" at 2793.5,-859 h60
  text "PLOT NAME =" at -228.5,-1064.34 h60
  text ".plot_File_Name" at 577,-1064.34 h60
  text "GENERATED    :" at 2250,-1064.34 h60
  text ".Print_Date" at 3119.5,-1064.34 h60
  text ".Print_Time" at 3848.5,-1064.34 h60
  text "TEXAS INSTRUMENTS" at 5113,-1064.34 h60
M6 Assembly Bottom:
  lines w10: -292.5,-727.33 6309.5,-727.33 ; -290.5,-930.67 6309.5,-930.67 ; 1115.5,-1140.5 1115.5,-937.67 ; 1737.5,-727.33 1737.5,-524 ; 2577.5,-727.33 2577.5,-524 ; 3844.5,-1134 3844.5,-524 ; 4733.5,-1134 6309,-1134 6309,-524 -292.5,-524 -292.5,-1134 2304.5,-1134 6309.5,-1134 6309.5,-524
  text "COMPONENTS MARKED 'DNP' SHOULD NOT BE POPULATED." at 6102,-318 h60
  text ".VariantName" at 5058,-434 h60
  text "ASSEMBLY VARIANT:" at 6097,-434 h60
  text ".VersionControl_RevNumber" at 1035.5,-656.17 h60
  text "SVN REV:" at 1541.5,-656.17 h60
  text ".PCB_Rev" at 2088,-656.17 h60
  text "REV:" at 2379.5,-656.17 h60
  text ".PRJ_Number" at 3224,-656.17 h60
  text "BOARD #:" at 3769.5,-656.17 h60
  text "PCB VIEWED FROM BOTTOM SIDE" at 6246,-656.17 h60
  text ".TID" at 3224,-859.5 h60
  text "TID #:" at 3769.5,-859.5 h60
  text "TEXAS INSTRUMENTS" at 904.5,-1064.84 h60
  text ".Print_Time" at 2169,-1064.84 h60
  text ".Print_Date" at 2898,-1064.84 h60
  text "GENERATED    :" at 3767.5,-1064.84 h60
  text ".plot_File_Name" at 5440.5,-1064.84 h60
  text "PLOT NAME =" at 6246,-1064.84 h60
M9 Title Sheet:
  drawing of 57 lines, arcs and shapes, not listed
  text "1" at 739.84,8036.5 h70
  text "2" at 3235.5,8036.5 h70
  text "3" at 5724.84,8036.5 h70
  text "4" at 8231.51,8036.5 h70
  text "5" at 10730.5,8036.5 h70
  text "6" at 13235.5,8036.5 h70
  text "A" at -416.5,6893.5 h70
  text "A" at 14383.5,6893.5 h70
  text "B" at -416.5,4513.5 h70
  text "B" at 14383.5,4513.5 h70
  text "C" at -416.5,2138.5 h70
  text "C" at 14383.5,2138.5 h70
  text "PROJECT TITLE:" at 11343.5,277.5 h45
  text ".PRJ_Title" at 11393.5,144.17 h70
  text "DESIGNED FOR:" at 11343.5,-23.5 h45
  text ".PRJ_Customer" at 11393.5,-163.5 h70
  text "D" at -416.5,-231.5 h70
  text "D" at 14383.5,-231.5 h70
  text "FILE NAME:" at 11343.5,-323.5 h45
  text ".PCB_File_Name_No_Path" at 11393.5,-443.5 h70
  text "Texas Instruments (TI) and/or its licensors do not warrant the accuracy or completeness of this specification" at 6374,-605.34 h45
  text "ENGINEER:" at 11343.5,-613.5 h45
  text "LAYOUT BY:" at 12848.5,-613.5 h45
  text "or any information contained therein. TI and/or its licensors do not warrant that this design will meet" at 6329.01,-718 h45
  text ".PRJ_Engineer" at 11393.5,-768.49 h70
  text ".PCB_Layout" at 12899,-768.49 h70
  text "the specifications, will be suitable for your application or fit for any particular purpose, or will operate in" at 6329.01,-830.67 h45
  text ".Layer_Name" at 577,-858.49 h60
  text "ALTIUM DESIGNER VERSION:" at 12848.5,-923.5 h45
  text "an implementation. TI and/or its licensors do not warrant that the design is production worthy. You should" at 6329.01,-943.33 h45
  text "completely validate and test your design implementation to confirm the system functionality for your application." at 6374,-1056 h45
  text ".print_Scale" at 11393.5,-1056.83 h70
  text ".Application_BuildNumber" at 12899,-1056.83 h70
  text "1" at 739.84,-1263.5 h70
  text "2" at 3235.5,-1263.5 h70
  text "3" at 5724.84,-1263.5 h70
  text "4" at 8231.51,-1263.5 h70
  text "5" at 10730.5,-1263.5 h70
  text "6" at 13235.5,-1263.5 h70
M10 Fab Notes:
  drawing of 189 lines, arcs and shapes, not listed
  text "DESIGN INFORMATION" at 12382.02,6356.17 h60
  text "MIN. TRACK WIDTH:" at 11737.46,6224.05 h60
  text "8" at 12833.7,6224.05 h60
  text "MIL" at 12988.46,6224.05 h60
  text "MIN. CLEARANCE:" at 11737.46,6099.92 h60
  text "0.2" at 12773.7,6099.93 h60
  text "mm" at 12988.46,6099.92 h60
  text "MIN. VIA PAD SIZE:" at 11737.46,5975.8 h60
  text "24" at 12803.71,5975.8 h60
  text "MIL" at 12988.46,5975.8 h60
  text "0.05mm (2MIL)" at 12432.46,5845.9 h60
  text "MINIMUM ANNULAR RING" at 11408.23,5837.67 h60
  text "EXTERNAL" at 13140.46,5837.67 h60
  text "PER" at 11608.23,5727.55 h60
  text "IPC-D-275 CLASS 2 LEVEL C" at 11828.23,5727.54 h60
  text "MIL, HOLES" at 13316.46,5627.07 h60
  text "+/-" at 12924,5618.48 h60
  text "+/-" at 13778,5618.48 h60
  text "REGISTRATION TOLERANCES:" at 11408.23,5617.42 h60
  text "METAL" at 12608,5617.42 h60
  text "5" at 13184.2,5617.42 h60
  text "3" at 14017.2,5617.42 h60
  text "MIL" at 14133.46,5617.42 h60
  text "HOLE SIZE TOLERANCE (UNLESS OTHERWISE SPECIFIED):" at 11408.23,5519.1 h60
  text "+/-" at 13778,5516.23 h60
  text "3" at 14017.2,5515.17 h60
  text "MIL" at 14133.46,5515.17 h60
  text "MATERIAL:" at 11333.46,5377.52 h60
  text "FR-4 High Tg" at 12319.9,5249 h60
  text "X" at 12175.46,5241.01 h60
  text "FR-408" at 11754.46,5236.49 h60
  text "OTHER" at 13242.46,5236.49 h60
  text "62 MIL (1.6mm) +/-10%" at 12074.56,5093.46 h60
  text "X" at 13241.87,5091.01 h60
  text "34 MIL" at 13769.68,5089.57 h60
  text "THICKNESS:" at 11408.23,5085.24 h60
  text "OTHER" at 13359.46,5085.24 h60
  text "TOLERANCE:" at 11408.23,4946.92 h60
  text "X" at 12256.46,4946.92 h60
  text "ANSI IPC-6012 TYPE 3 CLASS 2" at 12434.48,4946.92 h60
  text "OTHER +/-" at 12434.46,4802.73 h60
  text "BOW & TWIST:" at 11408.23,4657.54 h60
  text "X" at 12256.46,4657.54 h60
  text "ANSI IPC-6012 TYPE 3 CLASS 2" at 12434.48,4657.54 h60
  text "OTHER +/-" at 12434.46,4510.85 h60
  text "DRILLING:" at 11333.46,4380.23 h60
  text "NC_DRILL FILES" at 13094.46,4275.04 h60
  text "REFERENCE:" at 11408.23,4271.1 h60
  text "X" at 12065.46,4271.01 h60
  text "AS SHOWN" at 12243.46,4271.1 h60
  text "X" at 12966.46,4271.1 h60
  text "OTHER" at 13392.46,4128.85 h60
  text "PTH COPPER THICKNESS:" at 11407.91,4125.32 h60
  text "X" at 12547.14,4125.32 h60
  text "20-30 um" at 12675.14,4125.32 h60
  text "BOARD FINISH:" at 11333.46,3977.73 h60
  text "SILKSCREEN:" at 11488.68,3867.6 h60
  text "X" at 12446.46,3867.6 h60
  text "TOP" at 12563.46,3867.6 h60
  text "X" at 12956.46,3867.6 h60
  text "BOTTOM" at 13074.46,3867.6 h60
  text "SILKSCREEN COLOR:" at 11488.68,3712.41 h60
  text "X" at 12445.46,3712.41 h60
  text "WHITE" at 12563.46,3712.41 h60
  text "OTHER" at 13074.46,3712.41 h60
  text "X" at 12569.88,3574.8 h60
  text "GREEN" at 12694.46,3568.96 h60
  text "OTHER" at 13312.46,3568.96 h60
  text "SOLDER RESIST COLOR:" at 11488.68,3562.1 h60
  text "X" at 12576.46,3414.71 h60
  text "MATTE" at 12694.46,3414.71 h60
  text "SEMI-GLOSS" at 13312,3414.07 h60
  text "IMMERSION GOLD (ENIG)" at 12394.46,3241.94 h60
  text "ENEPIG" at 13732,3234.72 h60
  text "SURFACE FINISH:" at 11333.46,3233.72 h60
  text "X" at 12216.46,3233.72 h60
  text "IMM. TIN/SILVER OR EQUIV" at 11663,3096.4 h60
  text "OTHER" at 13094.46,3092.47 h60
  text "ARRAY/PANEL:" at 11333.46,2937.09 h60
  text "CUT AND TRIM PER M1 BOARD OUTLINE" at 12394.46,2928.87 h60
  text "N.C. ROUTE" at 12394.46,2792.9 h60
  text "X" at 13082.46,2792.9 h60
  text "V. SCORE" at 13260.46,2792.9 h60
  text "CERTIFICATION:" at 11333.46,2663.77 h60
  text "MATERIALS AND WORKMANSHIP FOR ALL PCBS" at 12058.46,2663.77 h60
  text "TO MEET OR EXCEED THE REQUIREMENTS OF:" at 12058.46,2569.71 h60
  text "X" at 11695.97,2441.08 h60
  text "ANSI IPC-A-600F CLASS ->" at 11823.96,2441.08 h60
  text "X" at 13471.97,2441.08 h60
  text "2" at 13581.96,2441.08 h60
  text "1" at 13266.96,2439.58 h60
  text "3" at 13935.96,2439.58 h60
  text "X" at 12507.97,2293.39 h60
  text "RoHS" at 12635.96,2293.39 h60
  text "OTHER" at 13280.36,2293.39 h60
  text "PER ORDER" at 13677.42,2293.39 h60
  text "ALL BOARDS MUST MEET OR EXCEED UL94-V0 REQUIREMENTS." at 11361,2139.57 h60
  text "PCB MUST BEAR THE UL94V-0 UL REGISTERED MATERIAL ID NUMBER" at 11361,2023.5 h60
  text "ADDITIONAL REQUIREMENTS:" at 11333.46,1854.08 h60
  text "MICROSECTION:" at 11408.23,1746.95 h60
  text "YES" at 12313.96,1746.95 h60
  text "REQUIRED" at 13175.46,1602.62 h60
  text "BARE BOARD ELEC. TEST:" at 11408.23,1599.76 h60
  text "NONE" at 12713.96,1599.76 h60
  text "X" at 13057.46,1599.76 h60
  text "PER ORDER" at 13767.46,1599.76 h60
  text "XX MIL VIAS REQUIRE NON-CONDUCTIVE FILL AND PLANARIZE" at 11576.38,1394.82 h59
  text "XX MIL VIAS REQUIRE CONDUCTIVE FILL AND PLANARIZE" at 11584.38,1290.84 h60
  text "OUTER XX MIL VIAS REQUIRE 50 OHM SINGLE-ENDED IMPEDANCE" at 11583.39,1127.46 h58
  text "LAYER 2 & 3 (INNER LAYERS) XX MIL WIDE, XX MIL SPACE / TRACES REQUIRE 100 OHM DIFFERENTIAL IMPEDANCE" at 11575.39,891.74 h60
  text ".Layer_Name" at 577,-858.49 h60
M11 Gerber Information:
  lines w10: -292,-930.17 6308,-930.17 ; -292,-726.83 6310,-726.83 ; -292,-523.5 -292,-1133.5 3713,-1133.5 6310,-1133.5 6310,-523.5 -291.5,-523.5 -291.5,-1133.5 1284,-1133.5 ; 2173,-1133.5 2173,-523.5 ; 3440,-726.83 3440,-523.5 ; 4280,-726.83 4280,-523.5 ; 4902,-1140 4902,-937.17
  text "ALL ARTWORK VIEWED FROM TOP SIDE" at -228.5,-655.67 h60
  text "BOARD #:" at 2248,-655.67 h60
  text ".PRJ_Number" at 2793.5,-655.67 h60
  text "REV:" at 3638,-655.67 h60
  text ".PCB_Rev" at 3929.5,-655.67 h60
  text "SVN REV:" at 4476,-655.67 h60
  text ".VersionControl_RevNumber" at 4982,-655.67 h60
  text "LAYER NAME =" at -228.5,-858.49 h60
  text "TID #:" at 2248,-859 h60
  text ".TID" at 2793.5,-859 h60
  text "PLOT NAME =" at -228.5,-1064.34 h60
  text ".plot_File_Name" at 577,-1064.34 h60
  text "GENERATED    :" at 2250,-1064.34 h60
  text ".Print_Date" at 3119.5,-1064.34 h60
  text ".Print_Time" at 3848.5,-1064.34 h60
  text "TEXAS INSTRUMENTS" at 5113,-1064.34 h60
M12 Stackup:
  drawing of 399 lines, arcs and shapes, not listed
  text "Layer" at 6464.68,7523.78 h60
  text "Name" at 6874.59,7523.78 h60
  text "Material" at 7804.33,7523.78 h60
  text "Thickness" at 8664.1,7523.78 h60
  text "Constant" at 9313.94,7523.78 h60
  text "Board Layer Stack" at 9883.8,7523.78 h60
  text "1" at 6464.68,7403.78 h60
  text "Top Overlay" at 6874.59,7403.78 h60
  text "2" at 6464.68,7283.78 h60
  text "Top Solder" at 6874.59,7283.78 h60
  text "Solder Resist" at 7804.33,7283.78 h60
  text "0.40mil" at 8664.1,7283.78 h60
  text "3.5" at 9313.94,7283.78 h60
  text "3" at 6464.68,7163.78 h60
  text "Top Layer" at 6874.59,7163.78 h60
  text "Copper" at 7804.33,7163.78 h60
  text "1.38mil" at 8664.1,7163.78 h60
  text "4" at 6464.68,7043.78 h60
  text "Dielectric1" at 6874.59,7043.78 h60
  text "FR-4" at 7804.33,7043.78 h60
  text "3.94mil" at 8664.1,7043.78 h60
  text "4.1" at 9313.94,7043.78 h60
  text "5" at 6464.68,6923.78 h60
  text "Layer2" at 6874.59,6923.78 h60
  text "Copper" at 7804.33,6923.78 h60
  text "0.71mil" at 8664.1,6923.78 h60
  text "6" at 6464.68,6803.78 h60
  text "Dielectric2" at 6874.59,6803.78 h60
  text "FR-4" at 7804.33,6803.78 h60
  text "7.87mil" at 8664.1,6803.78 h60
  text "4.1" at 9313.94,6803.78 h60
  text "7" at 6464.68,6683.78 h60
  text "Layer3" at 6874.59,6683.78 h60
  text "Copper" at 7804.33,6683.78 h60
  text "0.71mil" at 8664.1,6683.78 h60
  text "8" at 6464.68,6563.78 h60
  text "Dielectric3" at 6874.59,6563.78 h60
  text "FR-4" at 7804.33,6563.78 h60
  text "3.94mil" at 8664.1,6563.78 h60
  text "4.1" at 9313.94,6563.78 h60
  text "9" at 6464.68,6443.78 h60
  text "Layer4" at 6874.59,6443.78 h60
  text "Copper" at 7804.33,6443.78 h60
  text "0.71mil" at 8664.1,6443.78 h60
  text "10" at 6464.68,6323.78 h60
  text "Dielectric4" at 6874.59,6323.78 h60
  text "FR-4" at 7804.33,6323.78 h60
  text "7.87mil" at 8664.1,6323.78 h60
  text "4.1" at 9313.94,6323.78 h60
  text "11" at 6464.68,6203.78 h60
  text "Layer5" at 6874.59,6203.78 h60
  text "Copper" at 7804.33,6203.78 h60
  text "0.71mil" at 8664.1,6203.78 h60
  text "12" at 6464.68,6083.78 h60
  text "Dielectric5" at 6874.59,6083.78 h60
  text "FR-4" at 7804.33,6083.78 h60
  text "3.94mil" at 8664.1,6083.78 h60
  text "4.1" at 9313.94,6083.78 h60
  text "13" at 6464.68,5963.78 h60
  text "Bottom Layer" at 6874.59,5963.78 h60
  text "Copper" at 7804.33,5963.78 h60
  text "1.38mil" at 8664.1,5963.78 h60
  text "14" at 6464.68,5843.78 h60
  text "Bottom Solder" at 6874.59,5843.78 h60
  text "Solder Resist" at 7804.33,5843.78 h60
  text "0.40mil" at 8664.1,5843.78 h60
  text "3.5" at 9313.94,5843.78 h60
  text "15" at 6464.68,5723.78 h60
  text "Bottom Overlay" at 6874.59,5723.78 h60
  text ".Layer_Name" at 577,-858.49 h60
M13 Component Bodies Top:
  text ".Layer_Name" at 577,-858.49 h60
M14 Component Bodies Bottom:
  text ".Layer_Name" at 577,-858.49 h60
M15 Courtyards Top:
  text ".Layer_Name" at 577,-858.49 h60
M16 Courtyards Bottom:
  text ".Layer_Name" at 577,-858.49 h60
Drill Drawing:
  circle w10: c3399.18,1660.2 r22.14
  lines w10: 3377.04,1737.68 3377.04,1781.96 3421.32,1781.96 3421.32,1737.68 3377.04,1737.68 ; 3377.04,1848.38 3388.11,1859.44 3377.04,1870.51 3388.11,1870.51 3399.18,1881.58 3410.25,1870.51 3421.32,1870.51 3410.25,1859.44 3421.32,1848.38 3410.25,1848.38 3399.18,1837.31 3388.11,1848.38 3377.04,1848.38
  lines w12: 3336.28,1608.17 6449.22,1608.17 ; 3336.28,1907.04 6449.22,1907.04 ; 3651.91,1508.55 3651.91,2006.66 ; 3969.09,1508.55 3969.09,2006.66 ; 4590.84,1508.55 4590.84,2006.66 ; 4835.16,1508.55 4835.16,2006.66 ; 5195.5,1508.55 5195.5,2006.66 ; 5905.01,1508.55 5905.01,2006.66 ; 3336.28,1508.55 3336.28,2006.66 6449.22,2006.66 6449.22,1508.55 3336.28,1508.55
  text "Symbol" at 3396.05,1936.93 h72
  text "Quantity" at 3681.8,1936.93 h72
  text "Finished Hole Size" at 3998.98,1936.93 h72
  text "Plated" at 4620.73,1936.93 h72
  text "Hole Type" at 4865.05,1936.93 h72
  text "Drill Layer Pair" at 5225.39,1936.93 h72
  text "Hole Tolerance" at 5934.9,1936.93 h72
  text "104" at 3681.8,1837.31 h60
  text "7.87mil (0.200mm)" at 3998.98,1837.31 h60
  text "PTH" at 4620.73,1837.31 h60
  text "Round" at 4865.05,1837.31 h60
  text "Top Layer - Bottom Layer" at 5225.39,1837.31 h60
  text "4" at 3681.8,1737.68 h60
  text "16.00mil (0.406mm)" at 3998.98,1737.68 h60
  text "PTH" at 4620.73,1737.68 h60
  text "Round" at 4865.05,1737.68 h60
  text "Top Layer - Bottom Layer" at 5225.39,1737.68 h60
  text "3" at 3681.8,1638.06 h60
  text "40.00mil (1.016mm)" at 3998.98,1638.06 h60
  text "PTH" at 4620.73,1638.06 h60
  text "Round" at 4865.05,1638.06 h60
  text "Top Layer - Bottom Layer" at 5225.39,1638.06 h60
  text "111 Total" at 3681.8,1538.44 h60
  text ".Layer_Name" at 577,-858.49 h60
M17 Embedded Cavity:
  text ".Layer_Name" at 577,-858.49 h60
M18 Embedded Assembly:
  text ".Layer_Name" at 577,-858.49 h60
M19 Embedded Keepout:
  text ".Layer_Name" at 577,-858.49 h60

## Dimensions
0,-450 to 1000,-450 on M2 Board Dimensions
0,0 to 0,1875 on M2 Board Dimensions
0,0 to 3000,-0.2 on M2 Board Dimensions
